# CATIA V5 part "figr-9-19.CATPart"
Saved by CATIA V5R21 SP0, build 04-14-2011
Part number: Part3
Bounding box of the stored display mesh (mm): x -17.259 to 115.9, y -137.259 to 0, z -17.083 to 17.083
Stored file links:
  D:\CATIA V5R21 E-RESOURCES\CATIA-V5R21\catia-v5r21-prt\c09-catia-v5r20-prt\c09-catia-v5r21-figr-9-19.CATPart
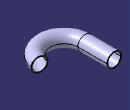
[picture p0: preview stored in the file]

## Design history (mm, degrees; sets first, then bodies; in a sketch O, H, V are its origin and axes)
Body1 (main body)
  Sketch1 on zx-plane, origin (0, 0, 0), H (-1, 0, 0), V (0, 0, 1)
    circle A1 centre (0, 0) radius 17.2586
  Sketch2 on xy-plane, origin (0, 0, 0), H (1, 0, 0), V (0, 1, 0)
    line L1 (0, 0) -> (0, -70)
    arc A1 centre (50, -70) radius 50 from (0, -70) to (50, -120) ccw
    arc A2 centre (50, -70) radius 50 from (50, -120) to (98.9898, -80) ccw
    vertical: L1 V
    tangency: A1 L1, A2 L1, A2 A1
  Rib1: profile Sketch1, centre curve Sketch2, thin wall 2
